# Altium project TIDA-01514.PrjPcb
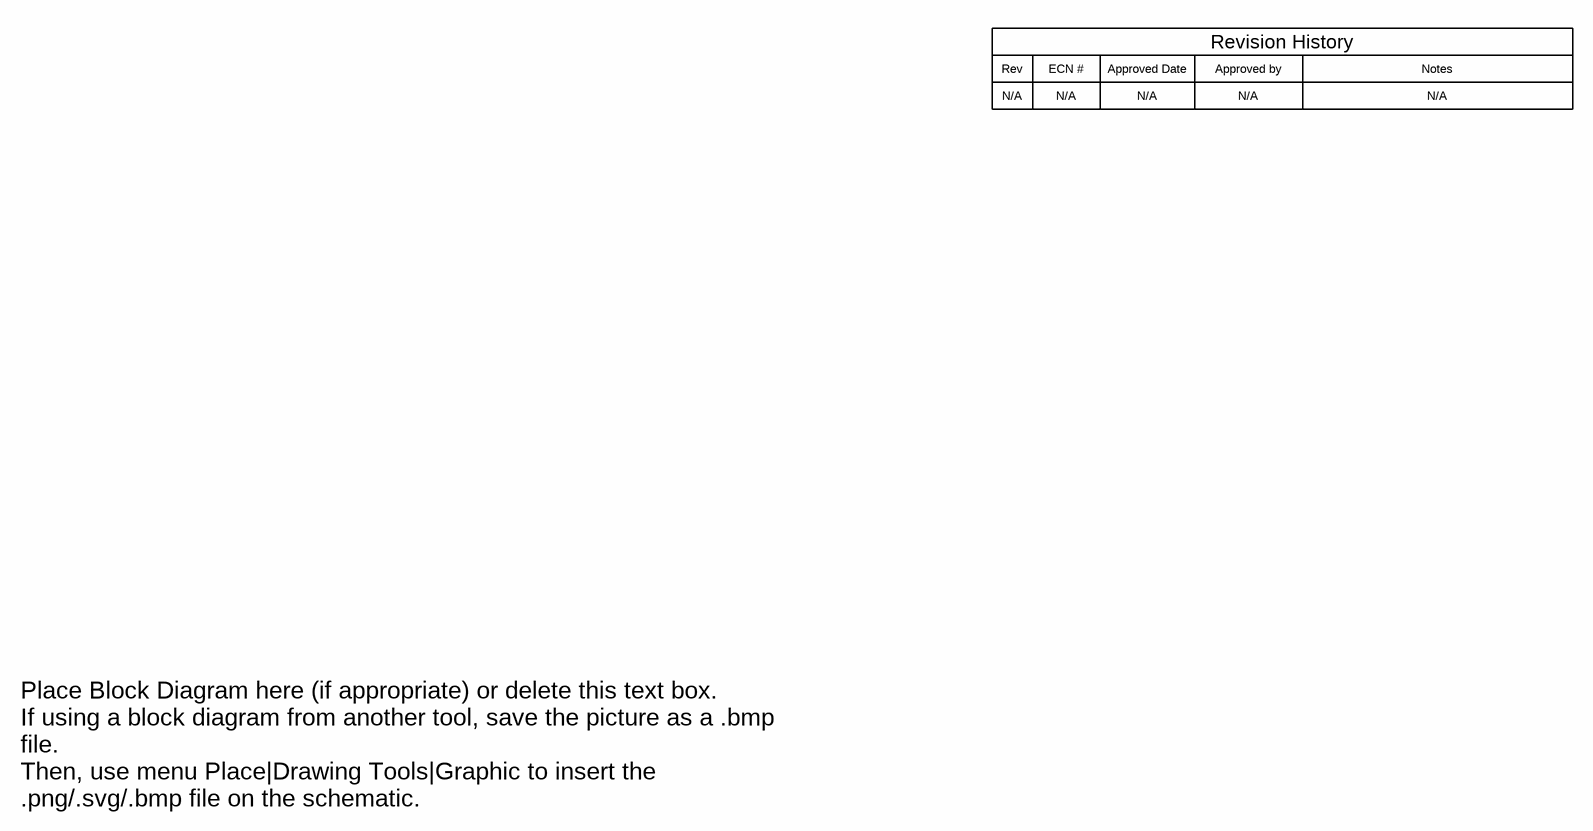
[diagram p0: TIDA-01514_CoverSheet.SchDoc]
TID: TIDA-01514; TechSupport: http://www.ti.com/support; SCH_Rev: E1; PRJ_Title: Protection For Antenna Module; PRJ_Number: TIDA-01514; PRJ_Engineer: Rakesh Panguloori; PRJ_Customer: Public Release; PCB_Rev: E1; PCB_Layout: Mansur; CopyrightYear: 2016
3 sheets, 64 parts. Net scope: global (net labels, ports and power ports of the same name join across sheets).
Board file: TIDA-01514.PcbDoc
Sheets:
  TIDA-01514_CoverSheet.SchDoc
  TIDA-01514.SchDoc
  TIDA-01514_Hardware.SchDoc

## Sheet TIDA-01514_CoverSheet.SchDoc
size 431 x 279 mm; Date: Not shown in title block; ApprovedBy: Not shown in title block; CheckedBy: Not shown in title block; Author: Not shown in title block; CompanyName: Not shown in title block; Engineer: Not shown in title block; Organization: Not shown in title block; Address1: Not shown in title block; Address2: Not shown in title block; Address3: Not shown in title block; Address4: Not shown in title block; DocumentNumber: 1; Revision: Use project parameter SCH_Rev; SheetNumber: 1; SheetTotal: 3; PageSetup: Record=PageOptions¦CenterHorizontal=True¦CenterVertical=True¦PrintScale=1.00¦XCorrection=1.00¦YCorrection=1.00¦PrintKind=0¦BorderSize=5000000¦LeftOffset=0¦BottomOffset=0¦Orientation=2¦PaperLength=1000¦PaperWidth=1000¦Scale=100¦PaperSource=15¦PrintQuality=600¦MediaType=1¦DitherType=10¦PaperKind=Letter¦PrintScaleMode=1

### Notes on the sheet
- Rev
- N/A
- ECN #
- Approved Date
- Approved by
- Revision History
- Notes
- Place Block Diagram here (if appropriate) or delete this text box.
  If using a block diagram from another tool, save the picture as a .bmp file.
  Then, use menu Place|Drawing Tools|Graphic to insert the .png/.svg/.bmp file on the schematic.

## Sheet TIDA-01514.SchDoc
size 431 x 279 mm; Date: Not shown in title block; ApprovedBy: Not shown in title block; CheckedBy: Not shown in title block; Author: Not shown in title block; CompanyName: Not shown in title block; Engineer: Not shown in title block; Organization: Not shown in title block; Address1: Not shown in title block; Address2: Not shown in title block; Address3: Not shown in title block; Address4: Not shown in title block; DocumentNumber: 1; Revision: Use project parameter SCH_Rev; SheetNumber: 2; SheetTotal: 3; PageSetup: Record=PageOptions¦CenterHorizontal=True¦CenterVertical=True¦PrintScale=1.00¦XCorrection=1.00¦YCorrection=1.00¦PrintKind=0¦BorderSize=5000000¦LeftOffset=0¦BottomOffset=0¦Orientation=2¦PaperLength=1000¦PaperWidth=1000¦Scale=100¦PaperSource=15¦PrintQuality=600¦MediaType=1¦DitherType=10¦PaperKind=Letter¦PrintScaleMode=1
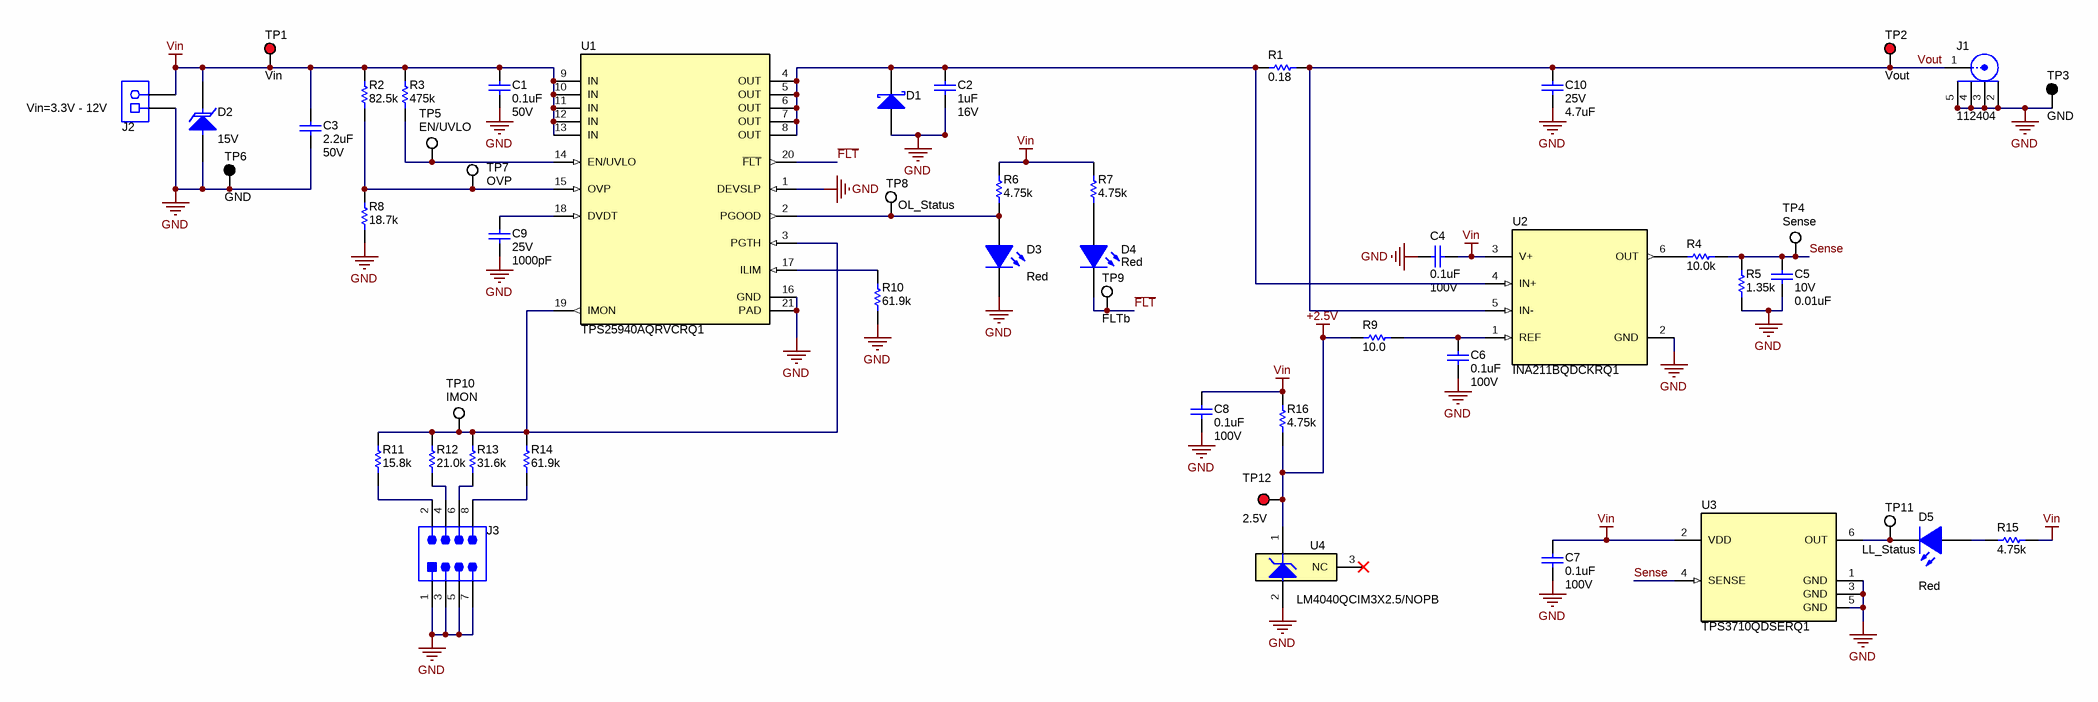
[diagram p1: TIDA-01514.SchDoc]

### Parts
C1  ValueDisplayed: 0.1uF  VDC_V: 50V  [0603]  (hidden comment: CMP-0007144-2)
C2  ValueDisplayed: 1uF  VDC_V: 16V  [0603]  (hidden comment: CMP-0007136-2)
C3  ValueDisplayed: 2.2uF  VDC_V: 50V  [1206_180]  (hidden comment: CMP-0008968-2)
C4  ValueDisplayed: 0.1uF  VDC_V: 100V  [0805_HV]  (hidden comment: CMP-0007886-2)
C5  VDC_V: 10V  ValueDisplayed: 0.01uF  [0603]  (hidden comment: 0603ZC103KAT2A)
C6  ValueDisplayed: 0.1uF  VDC_V: 100V  [0805_HV]  (hidden comment: CMP-0007886-2)
C7  ValueDisplayed: 0.1uF  VDC_V: 100V  [0805_HV]  (hidden comment: CMP-0007886-2)
C8  ValueDisplayed: 0.1uF  VDC_V: 100V  [0805_HV]  (hidden comment: CMP-0007886-2)
C9  VDC_V: 25V  ValueDisplayed: 1000pF  [0603]  (hidden comment: GRM188R71E102KA01D)
C10  VDC_V: 25V  ValueDisplayed: 4.7uF  [1206]  (hidden comment: C3216X7R1E475K085AB)
D1  CMP-0028546-1  [SOD-123FL]  (value not drawn)
D2  value 15V  [SMB]  (hidden comment: SMBJ15A-13-F)
D3  value Red  [LED_LTST-C170_Red]  (hidden comment: CMP-0002829-2)
D4  value Red  [LED_LTST-C170_Red]  (hidden comment: CMP-0002829-2)
D5  value Red  [LED_LTST-C170_Red]  (hidden comment: CMP-0002829-2)
J1  112404  [Amphenol_112404]
J2  CMP-0054973-1  [TEC_282841-2]  (value not drawn)
J3  PEC04DAAN  [CONN_PEC04DAAN]  (value not drawn)
R1  ValueDisplayed: 0.18  [1210]  (hidden comment: MCR25JZHFLR180)
R2  ValueDisplayed: 82.5k  [0603]  (hidden comment: CMP-0022620-2)
R3  ValueDisplayed: 475k  [0603]  (hidden comment: CMP-0022436-2)
R4  ValueDisplayed: 10.0k  [0603]  (hidden comment: CMP-0021998-2)
R5  ValueDisplayed: 1.35k  [0603]  (hidden comment: RT0603DRE071K35L)
R6  ValueDisplayed: 4.75k  [0603]  (hidden comment: CMP-0022456-2)
R7  ValueDisplayed: 4.75k  [0603]  (hidden comment: CMP-0022456-2)
R8  ValueDisplayed: 18.7k  [0603]  (hidden comment: CMP-0022098-2)
R9  ValueDisplayed: 10.0  [0603]  (hidden comment: CRCW060310R0FKEAHP)
R10  ValueDisplayed: 61.9k  [0603]  (hidden comment: CMP-0022536-2)
R11  ValueDisplayed: 15.8k  [0603]  (hidden comment: CRCW060315K8FKEA)
R12  ValueDisplayed: 21.0k  [0603]  (hidden comment: CRCW060321K0FKEA)
R13  ValueDisplayed: 31.6k  [0603]  (hidden comment: CRCW060331K6FKEA)
R14  ValueDisplayed: 61.9k  [0603]  (hidden comment: CMP-0022536-2)
R15  ValueDisplayed: 4.75k  [0603]  (hidden comment: CMP-0022456-2)
R16  ValueDisplayed: 4.75k  [0603]  (hidden comment: CMP-0022456-2)
TP1  Vin  [Keystone5010]
TP2  Vout  [Keystone5010]
TP3  GND  [Keystone5011]
TP4  Sense  [Keystone5012]
TP5  EN/UVLO  [Keystone5012]
TP6  GND  [Keystone5011]
TP7  OVP  [Keystone5012]
TP8  OL_Status  [Keystone5012]
TP9  FLTb  [Keystone5012]
TP10  IMON  [Keystone5012]
TP11  LL_Status  [Keystone5012]
TP12  2.5V  [Keystone5010]
U1  TPS25940AQRVCRQ1  [RVC0020A]
U2  INA211BQDCKRQ1  [DCK0006A_L]
U3  PartNumber: TPS3710QDSERQ1  [DSE0006A]  (hidden comment: TPS3710DSER)
U4  LM4040QCIM3X2.5/NOPB  [DBZ0003A_L]

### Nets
+2.5V: R9.1 R16.1 TP12.1 U4.1(K)
GND: C1.2 C2.2 C3.2 C4.1 C5.2 C6.1 C7.1 C8.1 C9.2 C10.2 D1.2(A) D2.2(A) D3.2(K) J1.2 J1.3 J1.4 J1.5 J2.1 J3.1 J3.3 J3.5 J3.7 R5.1 R8.1 R10.1 TP3.1 TP6.1 U1.1(DEVSLP) U1.16(GND) U1.21(PAD) U2.2(GND) U3.1(GND) U3.3(GND) U3.5(GND) U4.2(A)
Vin: C1.1 C3.1 C4.2 C7.2 C8.2 D2.1(K) J2.2 R2.2 R3.2 R6.1 R7.2 R15.2 R16.2 TP1.1 U1.9(IN) U1.10(IN) U1.11(IN) U1.12(IN) U1.13(IN) U2.3(V+) U3.2(VDD)
~{FLT}: D4.2(K) TP9.1 U1.20(~{FLT})
Sense: C5.1 R4.2 R5.2 TP4.1 U3.4(SENSE)
Vout: C10.1 J1.1 R1.2 TP2.1 U2.5(IN-)
NetC2_1: C2.1 D1.1(K) R1.1 U1.4(OUT) U1.5(OUT) U1.6(OUT) U1.7(OUT) U1.8(OUT) U2.4(IN+)
NetC6_2: C6.2 R9.2 U2.1(REF)
NetC9_1: C9.1 U1.18(DVDT)
NetD3_1: D3.1(A) R6.2 TP8.1 U1.2(PGOOD)
NetD4_1: D4.1(A) R7.1
NetD5_1: D5.1(A) R15.1
NetD5_2: D5.2(K) TP11.1 U3.6(OUT)
NetJ3_2: J3.2 R11.1
NetJ3_4: J3.4 R12.1
NetJ3_6: J3.6 R13.1
NetJ3_8: J3.8 R14.1
NetR2_1: R2.1 R8.2 TP7.1 U1.15(OVP)
NetR3_1: R3.1 TP5.1 U1.14(EN/UVLO)
NetR4_1: R4.1 U2.6(OUT)
NetR10_2: R10.2 U1.17(ILIM)
NetR11_2: R11.2 R12.2 R13.2 R14.2 TP10.1 U1.3(PGTH) U1.19(IMON)

Not connected (* = marked no-connect by the designer): U4 3(NC)*

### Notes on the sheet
- (near J2) Vin=3.3V - 12V

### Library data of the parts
C1 = CMP-0007144-2: CAP, CERM, 0.1 uF, 50 V, +/- 10%, X7R, 0603; PartNumber: GCM188R71H104KA57D; Manufacturer: MuRata; Polarized: N; Value: 0.1uF; U/M: EA; Cap_F: 100nF; ESR_ohm: 0.02; Value1: 0.02 ohm; IRMS_A: 1.84A; TaMin_C: -55°C; TaMax_C: 125°C; SizeArea_mm2: 1.28; SizeAreaWB_mm2: 4.68; SizeX_mm: 1.6; SizeY_mm: 0.8; SizeZ_mm: 1; AEC Category: Q200
C2 = CMP-0007136-2: CAP, CERM, 1 uF, 16 V, +/- 10%, X7R, AEC-Q200 Grade 1, 0603; PartNumber: GCM188R71C105KA64D; Manufacturer: MuRata; Polarized: N; Value: 1uF; U/M: EA; Cap_F: 1µF; Value1: Unknown; TaMin_C: -55°C; TaMax_C: 125°C; SizeArea_mm2: 1.28; SizeAreaWB_mm2: 4.68; SizeX_mm: 1.6; SizeY_mm: 0.8; SizeZ_mm: 1; AEC Category: Q200; AEC Qualified: Y
C3 = CMP-0008968-2: CAP, CERM, 2.2 uF, 50 V, +/- 10%, X7R, 1206; PartNumber: GRM31CR71H225KA88L; Manufacturer: MuRata; Polarized: N; Value: 2.2uF; U/M: EA; Cap_F: 2.2µF; Value1: Unknown; TaMin_C: -55°C; TaMax_C: 125°C; Cap_Case: 1206; SizeArea_mm2: 5.12; SizeAreaWB_mm2: 10.92; SizeX_mm: 3.2; SizeY_mm: 1.6; SizeZ_mm: 1.8; AEC Category: Q200
C4 = CMP-0007886-2: CAP, CERM, 0.1 uF, 100 V, +/- 10%, X7R, 0805; PartNumber: C2012X7R2A104K125AA; Manufacturer: TDK; Polarized: N; Value: 0.1uF; U/M: EA; Cap_F: 100nF; ESR_ohm: 0.020726; Value1: 0.020726 ohm; IRMS_A: 1.456A; TaMin_C: -55°C; TaMax_C: 125°C; Cap_Case: 0805; SizeArea_mm2: 2.5; SizeAreaWB_mm2: 6.75; SizeX_mm: 2; SizeY_mm: 1.25; SizeZ_mm: 1.45; AEC Category: Q200
C5 = CMP-0006814-2: CAP, CERM, 0.01 uF, 10 V, +/- 10%, X7R, 0603; Manufacturer: AVX; TaMin_C: -55°C; Polarized: N; SizeAreaWB_mm2: 4.68; Value1: Unknown; U/M: EA; Value: 0.01uF; TaMax_C: 125°C; SizeZ_mm: 1; SizeX_mm: 1.6; SizeY_mm: 0.8; SizeArea_mm2: 1.28; Cap_F: 10nF; AEC Category: Q200
C6-C8 = CMP-0007886-2: CAP, CERM, 0.1 uF, 100 V, +/- 10%, X7R, 0805; PartNumber: C2012X7R2A104K125AA; Manufacturer: TDK; Polarized: N; CompType: Capacitor; Value: 0.1uF; U/M: EA; Cap_F: 100nF; ESR_ohm: 0.020726; Value1: 0.020726 ohm; IRMS_A: 1.456A; TaMin_C: -55°C; TaMax_C: 125°C; Cap_Case: 0805; SizeArea_mm2: 2.5; SizeAreaWB_mm2: 6.75; SizeX_mm: 2; SizeY_mm: 1.25; SizeZ_mm: 1.45; AEC Category: Q200
C9 = CMP-0007402-2: CAP, CERM, 1000 pF, 25 V, +/- 10%, X7R, 0603; Manufacturer: MuRata; TaMin_C: -55°C; Polarized: N; SizeAreaWB_mm2: 4.68; Value1: Unknown; U/M: EA; Value: 1000pF; TaMax_C: 125°C; SizeZ_mm: 1; SizeX_mm: 1.6; SizeY_mm: 0.8; SizeArea_mm2: 1.28; CompType: Capacitor; Cap_F: 1nF; AEC Category: Q200
C10 = CMP-0008693-2: CAP, CERM, 4.7 uF, 25 V, +/- 10%, X7R, 1206; Manufacturer: TDK; TaMin_C: -55°C; Polarized: N; SizeAreaWB_mm2: 10.92; Value1: Unknown; U/M: EA; Value: 4.7uF; TaMax_C: 125°C; SizeZ_mm: 1.35; SizeX_mm: 3.2; SizeY_mm: 1.6; SizeArea_mm2: 5.12; Cap_F: 4.7µF; AEC Category: Q200
D1 = CMP-0028546-1: Diode, Schottky, 20 V, 1 A, SOD-123FL; PartNumber: MBR120LSFT1G; Manufacturer: ON Semiconductor; U/M: EA; Vf_V: 4.5dV; Value: 20V; Value1: 1A; Value2: 0.45V; TJmax_C: 125°C; RJC_CperW: 26; SizeAreaWB_mm2: 12.19; SizeArea_mm2: 5.94; SizeX_mm: 3.6; SizeY_mm: 1.65; SizeZ_mm: 0.98; AEC Category: Q101; Green_Lifecycle: Active; Green_REACh: Passed
D2 = CMP-0005545-2: Diode, TVS, Uni, 15 V, 24.4 Vc, SMB; Manufacturer: Diodes Inc.; Power_W: 5W; SizeAreaWB_mm2: 44.156; U/M: EA; SizeZ_mm: 2.6; SizeX_mm: 5.6; SizeY_mm: 3.81; SizeArea_mm2: 21.336; AEC Category: Q101
D3-D5 = CMP-0002829-2: LED, Red, SMD; PartNumber: LTST-C170KRKT; Manufacturer: Lite-On; Type: AlInGaP; Vf_V: 2V; Io_A: 20mA; Value1: W; SizeAreaWB_mm2: 6.75; SizeArea_mm2: 2.5; SizeX_mm: 2; SizeY_mm: 1.25; SizeZ_mm: 1.2; U/M: EA
J1 = CMP-0055424-1: Connector, TH, BNC; Manufacturer: Amphenol Connex; CT: TRUE; Green_REACh: Incomplete; CNHeader: FALSE; Green_Lifecycle: Not Set
J2 = CMP-0054973-1: Terminal Block, 2x1, 5.08mm, TH; PartNumber: 282841-2; Manufacturer: TE Connectivity; Green_Lifecycle: Active; Green_REACh: Passed; CNHeader: FALSE; CT: TRUE
J3 = CMP-0054542-1: Header, 100mil, 4x2, Tin, TH; Manufacturer: Sullins Connector Solutions; CNHeader: TRUE; Current_A: 3A; Green_Lifecycle: Not Set; Shrouded: N; Gender: Male; Green_REACh: Incomplete; Voltage_V: 1.8kV; Row_Count: 2; RowSpacing_mm: 2.54; CT: FALSE; Cert_UL: Y
R1 = CMP-0015173-2: RES, 0.18, 1%, 0.5 W, 1210; Manufacturer: Rohm; Power_W: 500mW; TempCo: 200 ppm/C; SizeAreaWB_mm2: 14.7; Value_Code: R180; U/M: EA; Value: 0.18; EIA_Code: E96; Res_ohm: 1.8d; SizeX_mm: 3.2; SizeY_mm: 2.5; SizeZ_mm: 1.35; Value2: 0.5W; SizeArea_mm2: 8; VDC_V: 0V; AEC Category: Q200
R2 = CMP-0022620-2: RES, 82.5 k, 1%, 0.1 W, 0603; PartNumber: CRCW060382K5FKEA; Manufacturer: Vishay-Dale; Value: 82.5k; Value_Code: 82k5; Power_W: 100mW; Value2: 0.1W; VDC_V: 75V; TempCo: 100 ppm/C; SizeArea_mm2: 1.28; SizeX_mm: 1.6; SizeY_mm: 0.8; SizeZ_mm: 1; EIA_Code: E96; U/M: EA; AEC Category: Q200
R3 = CMP-0022436-2: RES, 475 k, 1%, 0.1 W, 0603; PartNumber: CRCW0603475KFKEA; Manufacturer: Vishay-Dale; Value: 475k; Power_W: 100mW; Value2: 0.1W; VDC_V: 75V; TempCo: 100 ppm/C; SizeArea_mm2: 1.28; SizeX_mm: 1.6; SizeY_mm: 0.8; SizeZ_mm: 1; EIA_Code: E96; U/M: EA; AEC Category: Q200
R4 = CMP-0021998-2: RES, 10.0 k, 1%, 0.1 W, 0603; PartNumber: CRCW060310K0FKEA; Manufacturer: Vishay-Dale; Value: 10.0k; Res_ohm: 10k; Value_Code: 10k0; Power_W: 100mW; Value2: 0.1W; VDC_V: 75V; TempCo: 100 ppm/C; SizeArea_mm2: 1.28; SizeX_mm: 1.6; SizeY_mm: 0.8; SizeZ_mm: 1; EIA_Code: E96; U/M: EA; AEC Category: Q200
R5 = CMP-0024818-2: RES, 1.35 k, 0.5%, 0.1 W, 0603; Manufacturer: Yageo America; Power_W: 100mW; TempCo: 50 ppm/C; Value_Code: 1k35; U/M: EA; Value: 1.35k; EIA_Code: E192; SizeX_mm: 1.6; SizeY_mm: 0.8; SizeZ_mm: 1; Value2: 0.1W; SizeArea_mm2: 1.28; CompType: Resistor; VDC_V: 75V; AEC Category: Q200
R6 R7 R15 R16 = CMP-0022456-2: RES, 4.75 k, 1%, 0.1 W, 0603; PartNumber: CRCW06034K75FKEA; Manufacturer: Vishay-Dale; Value: 4.75k; Value_Code: 4k75; Power_W: 100mW; Value2: 0.1W; VDC_V: 75V; TempCo: 100 ppm/C; SizeArea_mm2: 1.28; SizeX_mm: 1.6; SizeY_mm: 0.8; SizeZ_mm: 1; EIA_Code: E96; U/M: EA; AEC Category: Q200
R8 = CMP-0022098-2: RES, 18.7 k, 1%, 0.1 W, 0603; PartNumber: CRCW060318K7FKEA; Manufacturer: Vishay-Dale; Value: 18.7k; Value_Code: 18k7; Power_W: 100mW; Value2: 0.1W; VDC_V: 75V; TempCo: 100 ppm/C; SizeArea_mm2: 1.28; SizeX_mm: 1.6; SizeY_mm: 0.8; SizeZ_mm: 1; EIA_Code: E96; U/M: EA; AEC Category: Q200
R9 = CMP-0022004-2: RES, 10.0, 1%, 0.25 W, 0603; Manufacturer: Vishay-Dale; Value: 10.0; Res_ohm: 10; Value_Code: 10R0; Power_W: 250mW; Value2: 0.25W; VDC_V: 75V; TempCo: 100 ppm/C; SizeArea_mm2: 1.28; SizeX_mm: 1.6; SizeY_mm: 0.8; SizeZ_mm: 1; EIA_Code: E96; U/M: EA; AEC Category: Q200
R10 = CMP-0022536-2: RES, 61.9 k, 1%, 0.1 W, 0603; PartNumber: CRCW060361K9FKEA; Manufacturer: Vishay-Dale; CompType: Resistor; Value: 61.9k; Value_Code: 61k9; Power_W: 100mW; Value2: 0.1W; VDC_V: 75V; TempCo: 100 ppm/C; SizeArea_mm2: 1.28; SizeX_mm: 1.6; SizeY_mm: 0.8; SizeZ_mm: 1; EIA_Code: E96; U/M: EA; AEC Category: Q200
R11 = CMP-0022068-2: RES, 15.8 k, 1%, 0.1 W, 0603; Manufacturer: Vishay-Dale; Power_W: 100mW; TempCo: 100 ppm/C; Value_Code: 15k8; U/M: EA; Value: 15.8k; EIA_Code: E96; SizeX_mm: 1.6; SizeY_mm: 0.8; SizeZ_mm: 1; Value2: 0.1W; SizeArea_mm2: 1.28; VDC_V: 75V; AEC Category: Q200
R12 = CMP-0022212-2: RES, 21.0 k, 1%, 0.1 W, 0603; Manufacturer: Vishay-Dale; Power_W: 100mW; TempCo: 100 ppm/C; Value_Code: 21k0; U/M: EA; Value: 21.0k; EIA_Code: E96; Res_ohm: 21k; SizeX_mm: 1.6; SizeY_mm: 0.8; SizeZ_mm: 1; Value2: 0.1W; SizeArea_mm2: 1.28; VDC_V: 75V; AEC Category: Q200
R13 = CMP-0022330-2: RES, 31.6 k, 1%, 0.1 W, 0603; Manufacturer: Vishay-Dale; Power_W: 100mW; TempCo: 100 ppm/C; Value_Code: 31k6; U/M: EA; Value: 31.6k; EIA_Code: E96; SizeX_mm: 1.6; SizeY_mm: 0.8; SizeZ_mm: 1; Value2: 0.1W; SizeArea_mm2: 1.28; VDC_V: 75V; AEC Category: Q200
R14 = CMP-0022536-2: RES, 61.9 k, 1%, 0.1 W, 0603; PartNumber: CRCW060361K9FKEA; Manufacturer: Vishay-Dale; Value: 61.9k; Value_Code: 61k9; Power_W: 100mW; Value2: 0.1W; VDC_V: 75V; TempCo: 100 ppm/C; SizeArea_mm2: 1.28; SizeX_mm: 1.6; SizeY_mm: 0.8; SizeZ_mm: 1; EIA_Code: E96; U/M: EA; AEC Category: Q200
TP1 TP2 TP12 = CMP-0055147-1: Test Point, Multipurpose, Red, TH; Manufacturer: Keystone; PartNumber: 5010; CNHeader: FALSE; Green_Lifecycle: Active; Green_REACh: Passed; ContactFinish: Silver; CT: TRUE
TP3 TP6 = CMP-0055148-1: Test Point, Multipurpose, Black, TH; Manufacturer: Keystone; PartNumber: 5011; CNHeader: FALSE; Green_Lifecycle: Active; Green_REACh: Passed; ContactFinish: Silver; CT: TRUE
TP4 TP5 TP7-TP11 = CMP-0055149-1: Test Point, Multipurpose, White, TH; Manufacturer: Keystone; PartNumber: 5012; CNHeader: FALSE; Green_Lifecycle: Active; Green_REACh: Passed; ContactFinish: Silver; CT: TRUE
U1 = CMP-0076737-1: 2.7V to 18V eFuse with Integrated Short-to-Battery Protection, RVC0020A (WQFN-20); Manufacturer: Texas Instruments; Alternate PartNumber: TPS25940AQRVCTQ1; SizeAreaWB_mm2: 20.0; SizeArea_mm2: 12.0; SizeZ_mm: 0.8; SizeY_mm: 4.0; U/M: EA; CompType: IC; SizeX_mm: 3.0
U2 = CMP-0076880-1: Automotive-Grade, Voltage Output, Low- or High-Side Measurement, Bidirectional, Zero-Drift Series, Current-Shunt Monitor, DCK0006A (SOT-SC70-6); Manufacturer: Texas Instruments; SizeAreaWB_mm2: 9.3; SizeArea_mm2: 4.2; SizeZ_mm: 1.1; SizeY_mm: 2.0; U/M: EA; CompType: IC; SizeX_mm: 2.1
U3 = CMP-0077206-1: Automotive Grade Wide VIN Voltage Detector, DSE0006A (WSON-6); Alternate Manufacturer: Texas Instruments; SizeAreaWB_mm2: 6.25; SizeZ_mm: 0.8; SizeX_mm: 1.5; SizeArea_mm2: 2.25; CompType: IC; AEC Qualified: Y; AEC Category: Q200
U4 = CMP-0076734-2: Precision Micropower Shunt Voltage Reference, DBZ0003A (SOT-23-3); Alternate Manufacturer: Texas Instruments; SizeArea_mm2: 7.5; SizeX_mm: 2.5; CompType: IC; SizeAreaWB_mm2: 14.0; SizeZ_mm: 1.12; SizeY_mm: 3.0; U/M: EA

## Sheet TIDA-01514_Hardware.SchDoc
size 431 x 279 mm; Date: Not shown in title block; ApprovedBy: Not shown in title block; CheckedBy: Not shown in title block; Author: Not shown in title block; CompanyName: Not shown in title block; Engineer: Not shown in title block; Organization: Not shown in title block; Address1: Not shown in title block; Address2: Not shown in title block; Address3: Not shown in title block; Address4: Not shown in title block; DocumentNumber: 1; Revision: Use project parameter SCH_Rev; SheetNumber: 3; SheetTotal: 3; PageSetup: Record=PageOptions¦CenterHorizontal=True¦CenterVertical=True¦PrintScale=1.00¦XCorrection=1.00¦YCorrection=1.00¦PrintKind=0¦BorderSize=5000000¦LeftOffset=0¦BottomOffset=0¦Orientation=2¦PaperLength=1000¦PaperWidth=1000¦Scale=100¦PaperSource=15¦PrintQuality=600¦MediaType=1¦DitherType=10¦PaperKind=Letter¦PrintScaleMode=1
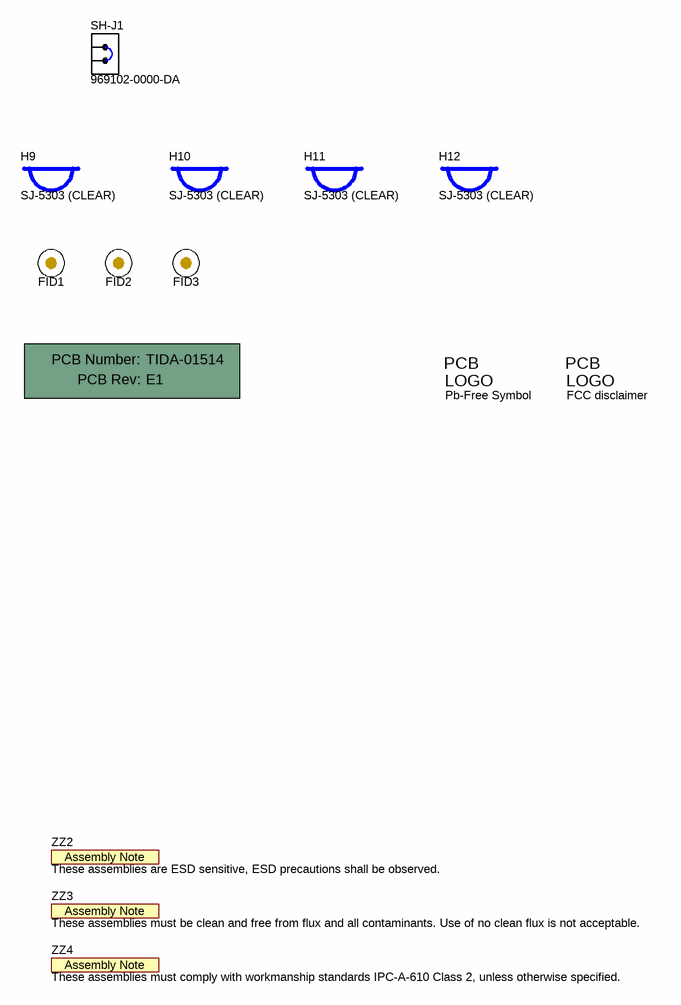
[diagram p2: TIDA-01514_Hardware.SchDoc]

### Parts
!PCB1  Printed Circuit Board  (value not drawn)  (mechanical)
FID1  Fiducial  [Fiducial10-20]  (value not drawn)
FID2  Fiducial  [Fiducial10-20]  (value not drawn)
FID3  Fiducial  [Fiducial10-20]  (value not drawn)
H9  SJ-5303 (CLEAR)  [Bumpon_SJ5003Transparent]
H10  SJ-5303 (CLEAR)  [Bumpon_SJ5003Transparent]
H11  SJ-5303 (CLEAR)  [Bumpon_SJ5003Transparent]
H12  SJ-5303 (CLEAR)  [Bumpon_SJ5003Transparent]
Logo2  Pb-Free Symbol  [Pb-Free_Overlay_Small]  (no BOM)
Logo3  FCC disclaimer  [FCC_disclaimer]  (no BOM)
SH-J1  969102-0000-DA  [SNT-100-BK-G]
ZZ2  These assemblies are ESD sensitive, ESD precautions shall be observed.  [AssemblyNote]  (no BOM)
ZZ3  These assemblies must be clean and free from flux and all contaminants. Use of no clean flux is not acceptable.  [AssemblyNote]  (no BOM)
ZZ4  These assemblies must comply with workmanship standards IPC-A-610 Class 2, unless otherwise specified.  [AssemblyNote]  (no BOM)

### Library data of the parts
!PCB1 = CMP-0003618-2: Manufacturer: Any; PartNumber: TIDA-01514
FID1-FID3 = CMP-0077181-1: Fiducial mark.  There is nothing to buy or mount.
H9-H12 = CMP-0003620-1: Bumpon, Hemisphere, 0.44 X 0.20, Clear; Manufacturer: 3M
Logo2 = CMP-0074839-1: SymbolCreator: a0412235; Library Reference: Logo
Logo3 = CMP-0074847-1: FCC_disclaimer
SH-J1 = CMP-0003614-1: Shunt, 100mil, Gold plated, Black; Alternate Manufacturer: Samtec; Manufacturer: 3M; Note: You can "mate" this to a header by matching the designator.  i.e. use SH-J3 for header J3; Value: 1x2
ZZ2 = CMP-0077236-1
ZZ3 = CMP-0077237-1
ZZ4 = CMP-0077238-1

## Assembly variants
001: not fitted C9 FID1 FID2 FID3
